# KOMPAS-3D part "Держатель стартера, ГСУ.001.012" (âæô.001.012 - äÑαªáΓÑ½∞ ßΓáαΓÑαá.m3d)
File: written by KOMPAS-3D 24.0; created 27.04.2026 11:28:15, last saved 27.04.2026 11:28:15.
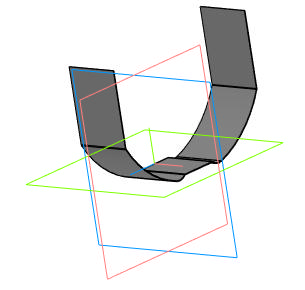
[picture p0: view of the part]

Document properties: Автор: User7; Полное имя файла: C:\Users\User7\Desktop\Двигатель мясорубки\ГСУ.001.012 - Держатель стартера.m3d

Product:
- Part/product: Держатель стартера  | designation ГСУ.001.012
    Масса: 0.003518

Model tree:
1. Эскиз:1
2. Обечайка:1
     Расстояние 1 = 16; Толщина листового тела = 0.25; Радиус сгиба = 0.5; Радиус сгиба = 0.5; Коэффициент = 0.4; Величина сгиба = 10; Радиус сгиба = 31.0798; Коэффициент = 0.4; Величина сгиба = 10; Радиус сгиба = 3; Коэффициент = 0.4; Величина сгиба = 10; Радиус сгиба = 0.5; Коэффициент = 0.4; Величина сгиба = 10; Радиус сгиба = 0.5; Коэффициент = 0.4; Величина сгиба = 10; Радиус сгиба = 3; Коэффициент = 0.4; Величина сгиба = 10; Радиус сгиба = 31.0798; Коэффициент = 0.4; Величина сгиба = 10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

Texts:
  ГСУ.001.012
